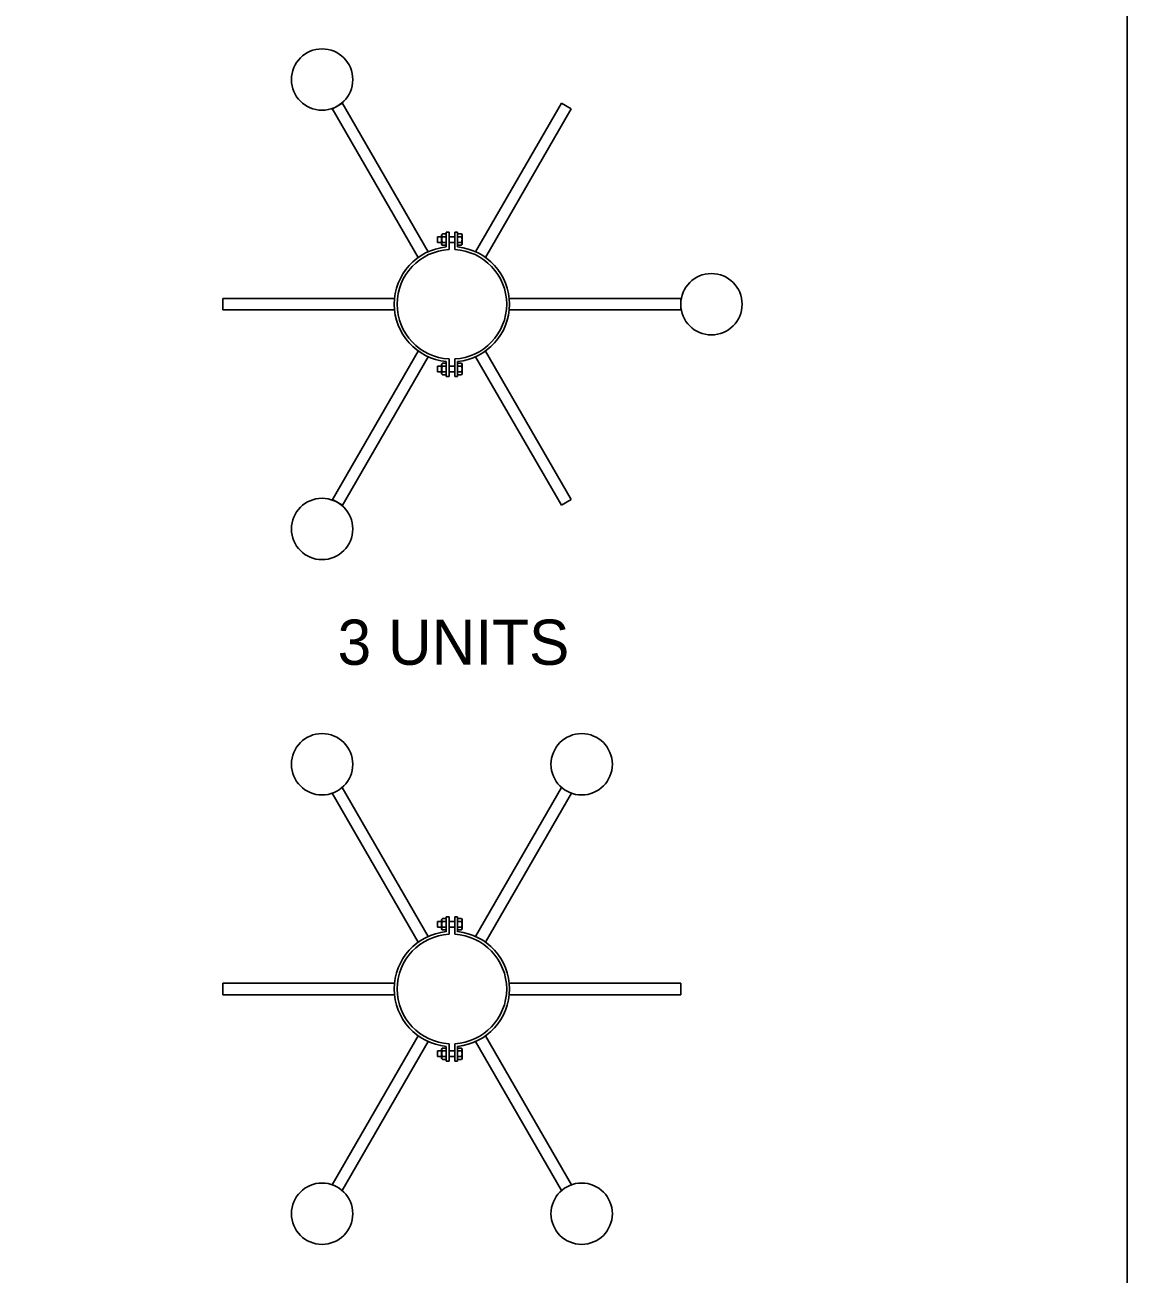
# Model space of a CAD drawing. Extents: x 99862 to 104211, y 98939 to 102076.
# Drawn here: x 102748.8 to 103151, y 101202 to 101658.1 of the extents above; entities that cross this region are included whole.
import ezdxf

# ---------------------------------------------------------------- set-up
doc = ezdxf.new("R2010")
doc.units = 0
for name, color, linetype in [('Level 1', 7, 'Continuous'), ('Level 2', 7, 'Continuous'), ('Level 20', 7, 'Continuous'), ('Level 4', 7, 'Continuous'), ('Level 7', 7, 'Continuous')]:
    doc.layers.add(name, color=color, linetype=linetype)

msp = doc.modelspace()

# ---------------------------------------------------------------- linework, layer by layer
at = {"layer": 'Level 1'}
msp.add_lwpolyline([(99862, 99999.5), (103151, 99999.5), (103151, 102075.5), (99862, 102075.5)], close=True, dxfattribs=at)
at = {"layer": 'Level 2'}
for p, q in [((102902.53, 101582.46), (102903.56, 101582.46)), ((102902.53, 101577.02), (102902.53, 101582.46)), ((102903.56, 101582.46), (102903.56, 101576.06)), ((102905.64, 101576.06), (102905.64, 101582.46)), ((102905.64, 101582.46), (102906.68, 101582.46)), ((102906.68, 101582.46), (102906.68, 101577.02)), ((102902.53, 101580.76), (102902.53, 101578.69)), ((102902.53, 101578.68), (102902.53, 101578.69)), ((102903.56, 101578.69), (102903.56, 101580.76)), ((102903.56, 101578.69), (102903.56, 101578.68)), ((102903.56, 101578.69), (102903.56, 101578.68)), ((102905.64, 101580.76), (102905.64, 101578.69)), ((102903.56, 101536.11), (102903.56, 101529.72)), ((102905.64, 101529.72), (102905.64, 101536.11)), ((102902.53, 101529.72), (102902.53, 101535.15)), ((102906.68, 101535.15), (102906.68, 101529.72)), ((102903.56, 101529.72), (102902.53, 101529.72)), ((102906.68, 101529.72), (102905.64, 101529.72)), ((102902.53, 101332.46), (102903.56, 101332.46)), ((102902.53, 101327.02), (102902.53, 101332.46)), ((102902.53, 101330.76), (102902.53, 101328.69)), ((102903.56, 101332.46), (102903.56, 101326.06)), ((102903.56, 101328.69), (102903.56, 101330.76)), ((102905.64, 101326.06), (102905.64, 101332.46)), ((102905.64, 101332.46), (102906.68, 101332.46)), ((102905.64, 101330.76), (102905.64, 101328.69)), ((102906.68, 101332.46), (102906.68, 101327.02)), ((102902.53, 101328.68), (102902.53, 101328.69)), ((102903.56, 101328.69), (102903.56, 101328.68)), ((102903.56, 101328.69), (102903.56, 101328.68)), ((102902.53, 101279.72), (102902.53, 101285.15)), ((102903.56, 101286.11), (102903.56, 101279.72)), ((102905.64, 101279.72), (102905.64, 101286.11)), ((102906.68, 101285.15), (102906.68, 101279.72)), ((102903.56, 101279.72), (102902.53, 101279.72)), ((102906.68, 101279.72), (102905.64, 101279.72))]:
    msp.add_line(p, q, dxfattribs=at)
for centre, radius, start, end in [((102904.6, 101556.09), 21.04, 95.6605, 264.3395), ((102904.6, 101556.09), 21.04, 275.6605, 84.3395), ((102904.6, 101556.09), 20, 92.9736, 267.0264), ((102904.6, 101556.09), 20, 272.9736, 87.0264), ((102904.6, 101306.09), 21.04, 95.6605, 264.3395), ((102904.6, 101306.09), 20, 92.9736, 267.0264), ((102904.6, 101306.09), 20, 272.9736, 87.0264), ((102904.6, 101306.09), 21.04, 275.6605, 84.3395)]:
    msp.add_arc(centre, radius, start, end, dxfattribs=at)
at = {"layer": 'Level 4'}
for p, q in [((102860.94, 101627.56), (102892.34, 101573.18)), ((102861.04, 101627.4), (102864.63, 101629.47)), ((102861.04, 101627.4), (102864.63, 101629.47)), ((102895.93, 101575.25), (102864.53, 101629.64)), ((102864.63, 101629.47), (102864.63, 101629.47)), ((102864.63, 101629.47), (102864.63, 101629.47)), ((102944.57, 101629.47), (102913.27, 101575.25)), ((102916.87, 101573.18), (102948.17, 101627.4)), ((102944.57, 101629.47), (102948.17, 101627.4)), ((102944.57, 101629.47), (102948.17, 101627.4)), ((102948.17, 101627.4), (102948.17, 101627.4)), ((102948.17, 101627.4), (102948.17, 101627.4)), ((102821.06, 101554.01), (102821.06, 101558.16)), ((102821.06, 101558.16), (102821.06, 101558.16)), ((102821.06, 101554.01), (102821.06, 101558.16)), ((102821.06, 101558.16), (102821.06, 101558.16)), ((102883.67, 101558.16), (102821.06, 101558.16)), ((102821.06, 101554.01), (102883.67, 101554.01)), ((102988.33, 101558.16), (102925.54, 101558.16)), ((102925.54, 101554.01), (102988.33, 101554.01)), ((102988.14, 101558.16), (102988.14, 101554.01)), ((102988.14, 101558.16), (102988.14, 101554.01)), ((102988.14, 101558.16), (102988.14, 101554.01)), ((102988.14, 101558.16), (102988.14, 101554.01)), ((102988.14, 101558.16), (102988.14, 101554.01)), ((102988.14, 101558.16), (102988.14, 101554.01)), ((102988.14, 101558.16), (102988.14, 101554.01)), ((102988.14, 101558.16), (102988.14, 101554.01)), ((102988.14, 101558.16), (102988.14, 101554.01)), ((102988.14, 101558.16), (102988.14, 101554.01)), ((102988.14, 101558.16), (102988.14, 101554.01)), ((102988.14, 101558.16), (102988.14, 101554.01)), ((102988.14, 101554.01), (102988.14, 101554.01)), ((102988.14, 101554.01), (102988.14, 101554.01)), ((102988.14, 101554.01), (102988.14, 101554.01)), ((102988.14, 101554.01), (102988.14, 101554.01)), ((102988.14, 101554.01), (102988.14, 101554.01)), ((102988.14, 101554.01), (102988.14, 101554.01)), ((102988.14, 101554.01), (102988.14, 101554.01)), ((102988.14, 101554.01), (102988.14, 101554.01)), ((102988.14, 101554.01), (102988.14, 101554.01)), ((102988.14, 101554.01), (102988.14, 101554.01)), ((102988.14, 101554.01), (102988.14, 101554.01)), ((102988.14, 101554.01), (102988.14, 101554.01)), ((102892.34, 101538.99), (102860.94, 101484.61)), ((102864.53, 101482.54), (102895.93, 101536.92)), ((102913.27, 101536.92), (102944.57, 101482.7)), ((102948.17, 101484.78), (102916.87, 101538.99)), ((102864.63, 101482.7), (102861.04, 101484.78)), ((102861.04, 101484.78), (102861.04, 101484.78)), ((102864.63, 101482.7), (102861.04, 101484.78)), ((102861.04, 101484.78), (102861.04, 101484.78)), ((102948.17, 101484.78), (102944.57, 101482.7)), ((102948.17, 101484.78), (102944.57, 101482.7)), ((102944.57, 101482.7), (102944.57, 101482.7)), ((102944.57, 101482.7), (102944.57, 101482.7)), ((102860.94, 101377.56), (102892.34, 101323.18)), ((102895.93, 101325.25), (102864.53, 101379.64)), ((102944.67, 101379.64), (102913.27, 101325.25)), ((102916.87, 101323.18), (102948.26, 101377.56)), ((102821.06, 101304.01), (102821.06, 101308.16)), ((102821.06, 101308.16), (102821.06, 101308.16)), ((102883.67, 101308.16), (102821.06, 101308.16)), ((102988.14, 101308.16), (102925.54, 101308.16)), ((102988.14, 101308.16), (102988.14, 101304.01)), ((102988.14, 101308.16), (102988.14, 101304.01)), ((102988.14, 101308.16), (102988.14, 101304.01)), ((102988.14, 101308.16), (102988.14, 101304.01)), ((102988.14, 101308.16), (102988.14, 101304.01)), ((102988.14, 101308.16), (102988.14, 101304.01)), ((102988.14, 101308.16), (102988.14, 101304.01)), ((102988.14, 101308.16), (102988.14, 101304.01)), ((102988.14, 101308.16), (102988.14, 101304.01)), ((102988.14, 101308.16), (102988.14, 101304.01)), ((102988.14, 101308.16), (102988.14, 101304.01)), ((102821.06, 101304.01), (102883.67, 101304.01)), ((102925.54, 101304.01), (102988.14, 101304.01)), ((102988.14, 101304.01), (102988.14, 101304.01)), ((102988.14, 101304.01), (102988.14, 101304.01)), ((102988.14, 101304.01), (102988.14, 101304.01)), ((102988.14, 101304.01), (102988.14, 101304.01)), ((102988.14, 101304.01), (102988.14, 101304.01)), ((102988.14, 101304.01), (102988.14, 101304.01)), ((102988.14, 101304.01), (102988.14, 101304.01)), ((102988.14, 101304.01), (102988.14, 101304.01)), ((102988.14, 101304.01), (102988.14, 101304.01)), ((102988.14, 101304.01), (102988.14, 101304.01)), ((102988.14, 101304.01), (102988.14, 101304.01)), ((102892.34, 101288.99), (102860.94, 101234.61)), ((102864.53, 101232.54), (102895.93, 101286.92)), ((102913.27, 101286.92), (102944.67, 101232.54)), ((102948.26, 101234.61), (102916.87, 101288.99))]:
    msp.add_line(p, q, dxfattribs=at)
for centre in [(102857.24, 101638.13), (102999.33, 101556.09), (102857.24, 101474.05), (102857.24, 101388.13), (102951.97, 101388.13), (102857.24, 101224.05), (102951.97, 101224.05)]:
    msp.add_circle(centre, 11.2, dxfattribs=at)
at = {"layer": 'Level 7'}
for p, q in [((102901.14, 101581.81), (102900.87, 101581.5)), ((102900.87, 101581.5), (102900.87, 101577.96)), ((102900.87, 101577.96), (102900.87, 101581.5)), ((102900.87, 101577.96), (102900.87, 101581.5)), ((102900.87, 101577.96), (102900.87, 101581.49)), ((102901.14, 101581.81), (102902.53, 101581.81)), ((102908.06, 101581.81), (102906.68, 101581.81)), ((102908.34, 101581.5), (102908.06, 101581.81)), ((102908.34, 101581.5), (102908.34, 101577.96)), ((102908.34, 101577.96), (102908.34, 101581.5)), ((102908.34, 101577.96), (102908.34, 101581.5)), ((102908.34, 101577.96), (102908.34, 101581.49)), ((102899.39, 101580.75), (102899.39, 101578.7)), ((102899.39, 101580.75), (102899.39, 101578.7)), ((102900.87, 101580.75), (102899.39, 101580.75)), ((102899.39, 101578.7), (102899.39, 101578.69)), ((102899.39, 101578.7), (102899.39, 101578.69)), ((102899.39, 101578.7), (102899.39, 101578.7)), ((102899.39, 101578.69), (102899.39, 101578.69)), ((102899.39, 101578.69), (102900.87, 101578.69)), ((102900.87, 101580.75), (102900.87, 101578.7)), ((102900.87, 101580.75), (102900.87, 101578.7)), ((102900.87, 101580.74), (102900.87, 101578.69)), ((102900.87, 101577.96), (102901.14, 101577.64)), ((102901.14, 101580.77), (102902.53, 101580.77)), ((102901.14, 101578.69), (102902.53, 101578.69)), ((102901.14, 101577.64), (102902.53, 101577.64)), ((102902.53, 101577.64), (102902.53, 101577.63)), ((102905.64, 101580.75), (102903.56, 101580.75)), ((102903.56, 101578.7), (102905.64, 101578.7)), ((102903.56, 101578.69), (102905.64, 101578.69)), ((102908.06, 101580.77), (102906.68, 101580.77)), ((102908.06, 101578.69), (102906.68, 101578.69)), ((102908.06, 101577.64), (102906.68, 101577.64)), ((102908.06, 101577.64), (102908.34, 101577.96)), ((102899.39, 101533.48), (102899.39, 101533.47)), ((102899.39, 101533.48), (102899.39, 101533.47)), ((102900.87, 101533.48), (102899.39, 101533.48)), ((102899.39, 101533.47), (102899.39, 101531.42)), ((102899.39, 101533.47), (102899.39, 101531.42)), ((102899.39, 101531.42), (102899.39, 101531.42)), ((102899.39, 101531.42), (102900.87, 101531.42)), ((102901.14, 101534.53), (102900.87, 101534.22)), ((102900.87, 101530.68), (102900.87, 101534.22)), ((102900.87, 101534.22), (102900.87, 101530.68)), ((102900.87, 101533.48), (102900.87, 101531.43)), ((102900.87, 101533.47), (102900.87, 101531.42)), ((102900.87, 101533.47), (102900.87, 101531.42)), ((102901.14, 101534.53), (102902.53, 101534.53)), ((102901.14, 101533.49), (102902.53, 101533.49)), ((102901.14, 101531.41), (102902.53, 101531.41)), ((102905.64, 101533.48), (102903.56, 101533.48)), ((102903.56, 101531.42), (102905.64, 101531.42)), ((102908.06, 101534.53), (102906.68, 101534.53)), ((102908.06, 101533.49), (102906.68, 101533.49)), ((102908.06, 101531.41), (102906.68, 101531.41)), ((102908.34, 101534.22), (102908.06, 101534.53)), ((102908.34, 101534.22), (102908.34, 101530.68)), ((102908.34, 101530.68), (102908.34, 101534.22)), ((102908.34, 101530.68), (102908.34, 101534.22)), ((102900.87, 101530.68), (102901.14, 101530.36)), ((102901.14, 101530.36), (102902.53, 101530.36)), ((102908.06, 101530.36), (102906.68, 101530.36)), ((102908.06, 101530.36), (102908.34, 101530.68)), ((102899.39, 101330.75), (102899.39, 101328.7)), ((102899.39, 101330.75), (102899.39, 101328.7)), ((102900.87, 101330.75), (102899.39, 101330.75)), ((102901.14, 101331.81), (102900.87, 101331.5)), ((102900.87, 101331.5), (102900.87, 101327.96)), ((102900.87, 101327.96), (102900.87, 101331.5)), ((102900.87, 101327.96), (102900.87, 101331.5)), ((102900.87, 101327.96), (102900.87, 101331.49)), ((102900.87, 101330.75), (102900.87, 101328.7)), ((102900.87, 101330.75), (102900.87, 101328.7)), ((102900.87, 101330.74), (102900.87, 101328.69)), ((102901.14, 101331.81), (102902.53, 101331.81)), ((102901.14, 101330.77), (102902.53, 101330.77)), ((102905.64, 101330.75), (102903.56, 101330.75)), ((102908.06, 101331.81), (102906.68, 101331.81)), ((102908.06, 101330.77), (102906.68, 101330.77)), ((102908.34, 101331.5), (102908.06, 101331.81)), ((102908.34, 101331.5), (102908.34, 101327.96)), ((102908.34, 101327.96), (102908.34, 101331.5)), ((102908.34, 101327.96), (102908.34, 101331.5)), ((102908.34, 101327.96), (102908.34, 101331.49)), ((102899.39, 101328.7), (102899.39, 101328.69)), ((102899.39, 101328.7), (102899.39, 101328.69)), ((102899.39, 101328.7), (102899.39, 101328.7)), ((102899.39, 101328.69), (102899.39, 101328.69)), ((102899.39, 101328.69), (102900.87, 101328.69)), ((102900.87, 101327.96), (102901.14, 101327.64)), ((102901.14, 101328.69), (102902.53, 101328.69)), ((102901.14, 101327.64), (102902.53, 101327.64)), ((102902.53, 101327.64), (102902.53, 101327.63)), ((102903.56, 101328.7), (102905.64, 101328.7)), ((102903.56, 101328.69), (102905.64, 101328.69)), ((102908.06, 101328.69), (102906.68, 101328.69)), ((102908.06, 101327.64), (102906.68, 101327.64)), ((102908.06, 101327.64), (102908.34, 101327.96)), ((102899.39, 101283.48), (102899.39, 101283.47)), ((102899.39, 101283.48), (102899.39, 101283.47)), ((102900.87, 101283.48), (102899.39, 101283.48)), ((102899.39, 101283.47), (102899.39, 101281.42)), ((102899.39, 101283.47), (102899.39, 101281.42)), ((102899.39, 101281.42), (102899.39, 101281.42)), ((102899.39, 101281.42), (102900.87, 101281.42)), ((102901.14, 101284.53), (102900.87, 101284.22)), ((102900.87, 101280.68), (102900.87, 101284.22)), ((102900.87, 101284.22), (102900.87, 101280.68)), ((102900.87, 101283.48), (102900.87, 101281.43)), ((102900.87, 101283.47), (102900.87, 101281.42)), ((102900.87, 101283.47), (102900.87, 101281.42)), ((102900.87, 101280.68), (102901.14, 101280.36)), ((102901.14, 101284.53), (102902.53, 101284.53)), ((102901.14, 101283.49), (102902.53, 101283.49)), ((102901.14, 101281.41), (102902.53, 101281.41)), ((102901.14, 101280.36), (102902.53, 101280.36)), ((102905.64, 101283.48), (102903.56, 101283.48)), ((102903.56, 101281.42), (102905.64, 101281.42)), ((102908.06, 101284.53), (102906.68, 101284.53)), ((102908.06, 101283.49), (102906.68, 101283.49)), ((102908.06, 101281.41), (102906.68, 101281.41)), ((102908.06, 101280.36), (102906.68, 101280.36)), ((102908.34, 101284.22), (102908.06, 101284.53)), ((102908.06, 101280.36), (102908.34, 101280.68)), ((102908.34, 101284.22), (102908.34, 101280.68)), ((102908.34, 101280.68), (102908.34, 101284.22)), ((102908.34, 101280.68), (102908.34, 101284.22))]:
    msp.add_line(p, q, dxfattribs=at)
for points in [[(102901.14, 101581.81), (102901.07, 101581.73), (102901.01, 101581.64), (102900.92, 101581.47), (102900.9, 101581.38), (102900.9, 101581.11), (102901, 101580.93), (102901.14, 101580.77)], [(102908.06, 101581.81), (102908.14, 101581.73), (102908.2, 101581.64), (102908.28, 101581.47), (102908.31, 101581.38), (102908.31, 101581.11), (102908.21, 101580.93), (102908.06, 101580.77)], [(102901.14, 101578.69), (102901.07, 101578.85), (102901.01, 101579.02), (102900.92, 101579.37), (102900.9, 101579.54), (102900.9, 101579.91), (102900.92, 101580.09), (102901.01, 101580.43), (102901.07, 101580.6), (102901.14, 101580.77)], [(102901.14, 101578.69), (102901.07, 101578.6), (102901.01, 101578.52), (102900.92, 101578.35), (102900.9, 101578.25), (102900.9, 101577.99), (102901, 101577.81), (102901.14, 101577.64)], [(102908.06, 101578.69), (102908.14, 101578.85), (102908.2, 101579.02), (102908.28, 101579.37), (102908.31, 101579.54), (102908.31, 101579.91), (102908.28, 101580.09), (102908.2, 101580.43), (102908.14, 101580.6), (102908.06, 101580.77)], [(102908.06, 101578.69), (102908.14, 101578.6), (102908.2, 101578.52), (102908.28, 101578.35), (102908.31, 101578.25), (102908.31, 101577.99), (102908.21, 101577.81), (102908.06, 101577.64)], [(102901.14, 101534.53), (102901.07, 101534.45), (102901.01, 101534.36), (102900.92, 101534.19), (102900.9, 101534.1), (102900.9, 101533.83), (102901, 101533.65), (102901.14, 101533.49)], [(102901.14, 101531.41), (102901.07, 101531.57), (102901.01, 101531.74), (102900.92, 101532.09), (102900.9, 101532.26), (102900.9, 101532.63), (102900.92, 101532.81), (102901.01, 101533.15), (102901.07, 101533.32), (102901.14, 101533.49)], [(102901.14, 101531.41), (102901.07, 101531.32), (102901.01, 101531.24), (102900.92, 101531.07), (102900.9, 101530.97), (102900.9, 101530.71), (102901, 101530.53), (102901.14, 101530.36)], [(102908.06, 101534.53), (102908.14, 101534.45), (102908.2, 101534.36), (102908.28, 101534.19), (102908.31, 101534.1), (102908.31, 101533.83), (102908.21, 101533.65), (102908.06, 101533.49)], [(102908.06, 101531.41), (102908.14, 101531.57), (102908.2, 101531.74), (102908.28, 101532.09), (102908.31, 101532.26), (102908.31, 101532.63), (102908.28, 101532.81), (102908.2, 101533.15), (102908.14, 101533.32), (102908.06, 101533.49)], [(102908.06, 101531.41), (102908.14, 101531.32), (102908.2, 101531.24), (102908.28, 101531.07), (102908.31, 101530.97), (102908.31, 101530.71), (102908.21, 101530.53), (102908.06, 101530.36)], [(102901.14, 101331.81), (102901.07, 101331.73), (102901.01, 101331.64), (102900.92, 101331.47), (102900.9, 101331.38), (102900.9, 101331.11), (102901, 101330.93), (102901.14, 101330.77)], [(102901.14, 101328.69), (102901.07, 101328.85), (102901.01, 101329.02), (102900.92, 101329.37), (102900.9, 101329.54), (102900.9, 101329.91), (102900.92, 101330.09), (102901.01, 101330.43), (102901.07, 101330.6), (102901.14, 101330.77)], [(102908.06, 101331.81), (102908.14, 101331.73), (102908.2, 101331.64), (102908.28, 101331.47), (102908.31, 101331.38), (102908.31, 101331.11), (102908.21, 101330.93), (102908.06, 101330.77)], [(102908.06, 101328.69), (102908.14, 101328.85), (102908.2, 101329.02), (102908.28, 101329.37), (102908.31, 101329.54), (102908.31, 101329.91), (102908.28, 101330.09), (102908.2, 101330.43), (102908.14, 101330.6), (102908.06, 101330.77)], [(102901.14, 101328.69), (102901.07, 101328.6), (102901.01, 101328.52), (102900.92, 101328.35), (102900.9, 101328.25), (102900.9, 101327.99), (102901, 101327.81), (102901.14, 101327.64)], [(102908.06, 101328.69), (102908.14, 101328.6), (102908.2, 101328.52), (102908.28, 101328.35), (102908.31, 101328.25), (102908.31, 101327.99), (102908.21, 101327.81), (102908.06, 101327.64)], [(102901.14, 101284.53), (102901.07, 101284.45), (102901.01, 101284.36), (102900.92, 101284.19), (102900.9, 101284.1), (102900.9, 101283.83), (102901, 101283.65), (102901.14, 101283.49)], [(102901.14, 101281.41), (102901.07, 101281.57), (102901.01, 101281.74), (102900.92, 101282.09), (102900.9, 101282.26), (102900.9, 101282.63), (102900.92, 101282.81), (102901.01, 101283.15), (102901.07, 101283.32), (102901.14, 101283.49)], [(102901.14, 101281.41), (102901.07, 101281.32), (102901.01, 101281.24), (102900.92, 101281.07), (102900.9, 101280.97), (102900.9, 101280.71), (102901, 101280.53), (102901.14, 101280.36)], [(102908.06, 101284.53), (102908.14, 101284.45), (102908.2, 101284.36), (102908.28, 101284.19), (102908.31, 101284.1), (102908.31, 101283.83), (102908.21, 101283.65), (102908.06, 101283.49)], [(102908.06, 101281.41), (102908.14, 101281.57), (102908.2, 101281.74), (102908.28, 101282.09), (102908.31, 101282.26), (102908.31, 101282.63), (102908.28, 101282.81), (102908.2, 101283.15), (102908.14, 101283.32), (102908.06, 101283.49)], [(102908.06, 101281.41), (102908.14, 101281.32), (102908.2, 101281.24), (102908.28, 101281.07), (102908.31, 101280.97), (102908.31, 101280.71), (102908.21, 101280.53), (102908.06, 101280.36)]]:
    msp.add_open_spline(points, degree=3, dxfattribs=at)

# ---------------------------------------------------------------- texts
at = {"layer": 'Level 20'}
msp.add_text('3 UNITS', height=16.5, dxfattribs=at).set_placement((102862.89, 101424.45))

doc.saveas('drawing.dxf')
